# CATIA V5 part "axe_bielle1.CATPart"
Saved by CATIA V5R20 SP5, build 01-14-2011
Part number: axe_bielle1
Bounding box of the stored display mesh (mm): x -2 to 5, y -1 to 1, z -0.951 to 0.951
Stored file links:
  F:\PROJ IAO\CATIA\axe_bielle1.CATPart
  F:\PROJ IAO\CATIA\Assemblage.CATProduct
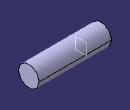
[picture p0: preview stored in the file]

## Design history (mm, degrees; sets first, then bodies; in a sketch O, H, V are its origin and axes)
Set1
  Plane1: linked copy from another document
Body1 (main body)
  Sketch1 on Plane1, origin (0, 0, 0), H (0, 1, 0), V (0, 0, 1)
    circle A1 centre (0, 0) radius 1
    point P1 (-1, 0)
    radius A1 = 1
    coincidence: A1 P1, P1 H
  Pad1: profile Sketch1, direction (1, 0, 0), length 5
  Pad2: profile start face of Pad1, direction along Plane1, length 5, opposite side length 2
